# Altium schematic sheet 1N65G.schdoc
size 127 x 101 mm
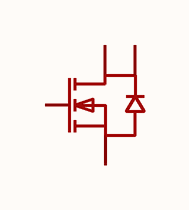
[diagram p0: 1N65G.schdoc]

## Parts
Q?  1n65g  [SOT-223-4_L6.5-W3.5-P2.30-LS7.0-BR]  (value not drawn)

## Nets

Not connected (* = marked no-connect by the designer): Q? 1(G) 2(D) 3(S) 4(D)

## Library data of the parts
Q? = 1n65g: 数量:1个N沟道;漏源电压(Vdss):650V;连续漏极电流(Id):1A;导通电阻(RDS(on)):11Ω@10V;耗散功率(Pd):-;阈值电压(Vgs(th)):4V@250uA;; Manufacturer: UMW(友台半导体); AddInBom: yes; ModelId: 925194bf9823436183a3e0b978a8d076; ModelName: SOT-223-4P_L6.5-W3.5-H1.6-LS7.0-P2.30; ModelTransform: 279.89794,255.905,0,180,0,0,-0.0005,-0.0005,0; Number: 1个N沟道; Drain to Source Voltage: 650V; Current - Continuous Drain(Id): 1A; Gate Charge(Qg): 4.8nC@10V; Input Capacitance(Ciss): 150pF; Reverse Transfer Capacitance (Crss@Vds): 5.4pF; Type: N沟道; Output Capacitance(Coss): 25pF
